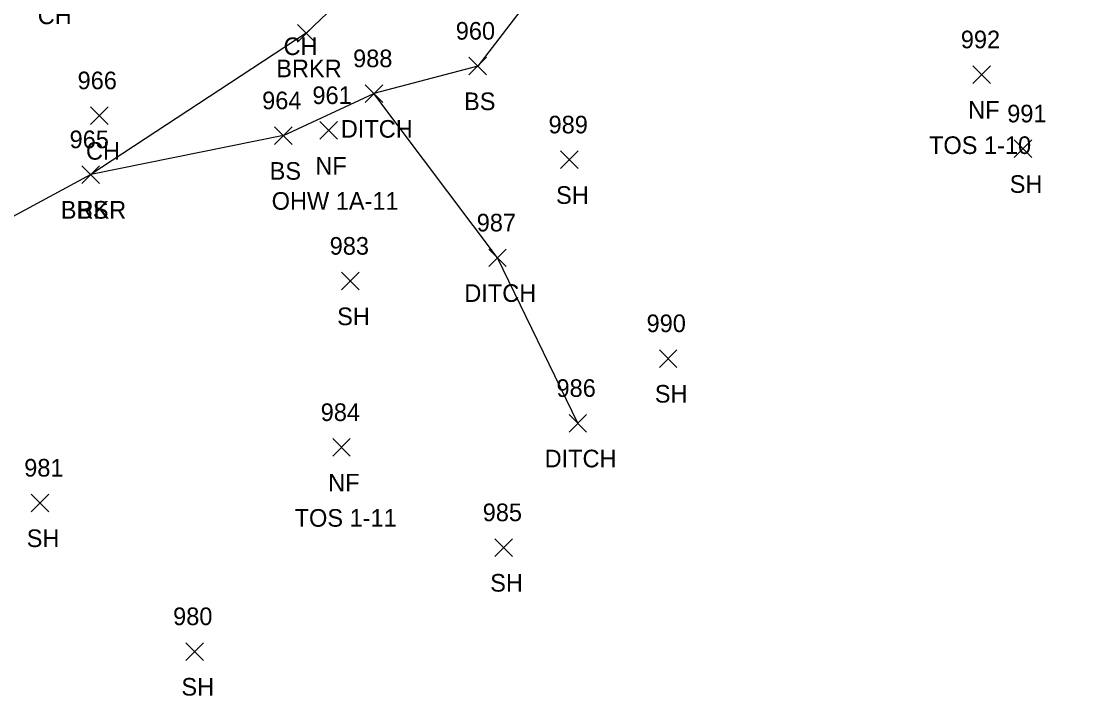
# Model space of a CAD drawing. Extents: x 1528286 to 1556263, y 492387 to 508952.
# Drawn here: x 1528421 to 1528541.2, y 492460.9 to 492537.5 of the extents above; entities that cross this region are included whole.
import ezdxf

# ---------------------------------------------------------------- set-up
doc = ezdxf.new("R2010")
doc.units = 0
for name, color, linetype in [('D_A', 7, 'Continuous'), ('D_I', 7, 'Continuous'), ('D_TIC', 7, 'Continuous'), ('DD', 7, 'Continuous'), ('L_A', 7, 'Continuous'), ('L_C', 7, 'Continuous'), ('L_I', 7, 'Continuous'), ('L_TIC', 7, 'Continuous'), ('LAWE', 7, 'Continuous'), ('LELB', 7, 'Continuous')]:
    doc.layers.add(name, color=color, linetype=linetype)

msp = doc.modelspace()

# ---------------------------------------------------------------- linework, layer by layer
at = {"layer": 'D_TIC'}
for points in [[(1528460.08, 492528.26), (1528462.08, 492530.26)], [(1528462.08, 492528.26), (1528460.08, 492530.26)], [(1528460.08, 492528.26), (1528462.08, 492530.26)], [(1528462.08, 492528.26), (1528460.08, 492530.26)], [(1528474.11, 492509.62), (1528476.11, 492511.62)], [(1528476.11, 492509.62), (1528474.11, 492511.62)], [(1528474.11, 492509.62), (1528476.11, 492511.62)], [(1528476.11, 492509.62), (1528474.11, 492511.62)], [(1528483.23, 492490.84), (1528485.23, 492492.84)], [(1528485.23, 492490.84), (1528483.23, 492492.84)], [(1528483.23, 492490.84), (1528485.23, 492492.84)], [(1528485.23, 492490.84), (1528483.23, 492492.84)]]:
    msp.add_lwpolyline(points, dxfattribs=at)
at = {"layer": 'DD'}
msp.add_lwpolyline([(1528484.23, 492491.84), (1528475.11, 492510.62), (1528461.08, 492529.26)], dxfattribs=at)
msp.add_lwpolyline([(1528484.23, 492491.84), (1528475.11, 492510.62), (1528461.08, 492529.26)], dxfattribs=at)
at = {"layer": 'L_TIC'}
for points in [[(1528452.39, 492535.12), (1528454.39, 492537.12)], [(1528454.39, 492535.12), (1528452.39, 492537.12)], [(1528452.39, 492535.12), (1528454.39, 492537.12)], [(1528454.39, 492535.12), (1528452.39, 492537.12)], [(1528471.87, 492531.39), (1528473.87, 492533.39)], [(1528473.87, 492531.39), (1528471.87, 492533.39)], [(1528471.87, 492531.39), (1528473.87, 492533.39)], [(1528473.87, 492531.39), (1528471.87, 492533.39)], [(1528529.09, 492530.41), (1528531.09, 492532.41)], [(1528531.09, 492530.41), (1528529.09, 492532.41)], [(1528529.09, 492530.41), (1528531.09, 492532.41)], [(1528531.09, 492530.41), (1528529.09, 492532.41)], [(1528428.88, 492525.76), (1528430.88, 492527.76)], [(1528430.88, 492525.76), (1528428.88, 492527.76)], [(1528428.88, 492525.76), (1528430.88, 492527.76)], [(1528430.88, 492525.76), (1528428.88, 492527.76)], [(1528454.94, 492524.08), (1528456.94, 492526.08)], [(1528456.94, 492524.08), (1528454.94, 492526.08)], [(1528454.94, 492524.08), (1528456.94, 492526.08)], [(1528456.94, 492524.08), (1528454.94, 492526.08)], [(1528449.79, 492523.49), (1528451.79, 492525.49)], [(1528451.79, 492523.49), (1528449.79, 492525.49)], [(1528449.79, 492523.49), (1528451.79, 492525.49)], [(1528451.79, 492523.49), (1528449.79, 492525.49)], [(1528533.79, 492522), (1528535.79, 492524)], [(1528535.79, 492522), (1528533.79, 492524)], [(1528533.79, 492522), (1528535.79, 492524)], [(1528535.79, 492522), (1528533.79, 492524)], [(1528482.28, 492520.75), (1528484.28, 492522.75)], [(1528484.28, 492520.75), (1528482.28, 492522.75)], [(1528482.28, 492520.75), (1528484.28, 492522.75)], [(1528484.28, 492520.75), (1528482.28, 492522.75)], [(1528427.92, 492519.07), (1528429.92, 492521.07)], [(1528429.92, 492519.07), (1528427.92, 492521.07)], [(1528427.92, 492519.07), (1528429.92, 492521.07)], [(1528429.92, 492519.07), (1528427.92, 492521.07)], [(1528427.92, 492519.07), (1528429.92, 492521.07)], [(1528429.92, 492519.07), (1528427.92, 492521.07)], [(1528427.92, 492519.07), (1528429.92, 492521.07)], [(1528429.92, 492519.07), (1528427.92, 492521.07)], [(1528457.41, 492506.98), (1528459.41, 492508.98)], [(1528459.41, 492506.98), (1528457.41, 492508.98)], [(1528457.41, 492506.98), (1528459.41, 492508.98)], [(1528459.41, 492506.98), (1528457.41, 492508.98)], [(1528493.49, 492498.19), (1528495.49, 492500.19)], [(1528495.49, 492498.19), (1528493.49, 492500.19)], [(1528493.49, 492498.19), (1528495.49, 492500.19)], [(1528495.49, 492498.19), (1528493.49, 492500.19)], [(1528456.39, 492488.1), (1528458.39, 492490.1)], [(1528458.39, 492488.1), (1528456.39, 492490.1)], [(1528456.39, 492488.1), (1528458.39, 492490.1)], [(1528458.39, 492488.1), (1528456.39, 492490.1)], [(1528422.15, 492481.79), (1528424.15, 492483.79)], [(1528424.15, 492481.79), (1528422.15, 492483.79)], [(1528422.15, 492481.79), (1528424.15, 492483.79)], [(1528424.15, 492481.79), (1528422.15, 492483.79)], [(1528474.8, 492476.73), (1528476.8, 492478.73)], [(1528476.8, 492476.73), (1528474.8, 492478.73)], [(1528474.8, 492476.73), (1528476.8, 492478.73)], [(1528476.8, 492476.73), (1528474.8, 492478.73)], [(1528439.72, 492464.93), (1528441.72, 492466.93)], [(1528441.72, 492464.93), (1528439.72, 492466.93)], [(1528439.72, 492464.93), (1528441.72, 492466.93)], [(1528441.72, 492464.93), (1528439.72, 492466.93)]]:
    msp.add_lwpolyline(points, dxfattribs=at)
at = {"layer": 'LAWE'}
msp.add_lwpolyline([(1528645.44, 492730.64), (1528651.62, 492718.64), (1528645.74, 492704.77), (1528631.81, 492684.8), (1528615.48, 492671.09), (1528597.13, 492648.32), (1528570.32, 492633.93), (1528549.93, 492614.14), (1528527.11, 492580.82), (1528486.91, 492550.69), (1528466.24, 492548.44), (1528453.39, 492536.12), (1528428.92, 492520.07), (1528405.49, 492507.44), (1528391.91, 492487.09), (1528384.54, 492464.65)], dxfattribs=at)
msp.add_lwpolyline([(1528645.44, 492730.64), (1528651.62, 492718.64), (1528645.74, 492704.77), (1528631.81, 492684.8), (1528615.48, 492671.09), (1528597.13, 492648.32), (1528570.32, 492633.93), (1528549.93, 492614.14), (1528527.11, 492580.82), (1528486.91, 492550.69), (1528466.24, 492548.44), (1528453.39, 492536.12), (1528428.92, 492520.07), (1528405.49, 492507.44), (1528391.91, 492487.09), (1528384.54, 492464.65)], dxfattribs=at)
at = {"layer": 'LELB'}
for points in [[(1528653.27, 492717.81), (1528645.74, 492704.77), (1528631.81, 492684.8), (1528615.48, 492671.09), (1528597.13, 492648.32), (1528570.32, 492633.93), (1528549.93, 492614.14), (1528527.11, 492580.82), (1528486.91, 492550.69), (1528472.87, 492532.39)], [(1528653.27, 492717.81), (1528645.74, 492704.77), (1528631.81, 492684.8), (1528615.48, 492671.09), (1528597.13, 492648.32), (1528570.32, 492633.93), (1528549.93, 492614.14), (1528527.11, 492580.82), (1528486.91, 492550.69), (1528472.87, 492532.39)], [(1528472.87, 492532.39), (1528461.08, 492529.26)], [(1528472.87, 492532.39), (1528461.08, 492529.26)], [(1528450.79, 492524.49), (1528461.08, 492529.26)], [(1528450.79, 492524.49), (1528461.08, 492529.26)], [(1528450.79, 492524.49), (1528428.92, 492520.07), (1528405.49, 492507.44), (1528391.91, 492487.09), (1528384.54, 492464.65)], [(1528450.79, 492524.49), (1528428.92, 492520.07), (1528405.49, 492507.44), (1528391.91, 492487.09), (1528384.54, 492464.65)]]:
    msp.add_lwpolyline(points, dxfattribs=at)

# ---------------------------------------------------------------- texts
at = {"layer": 'D_A'}
for p in [(1528457.31, 492524.26), (1528457.31, 492524.26), (1528471.34, 492505.62), (1528471.34, 492505.62), (1528480.46, 492486.84), (1528480.46, 492486.84)]:
    msp.add_text('DITCH', height=2, dxfattribs=at).set_placement(p)
at = {"layer": 'D_I'}
for s, p in [('988', (1528458.71, 492532.26)), ('988', (1528458.71, 492532.26)), ('987', (1528472.75, 492513.62)), ('987', (1528472.75, 492513.62)), ('986', (1528481.81, 492494.84)), ('986', (1528481.81, 492494.84))]:
    msp.add_text(s, height=2, dxfattribs=at).set_placement(p)
at = {"layer": 'L_A'}
for s, p in [('CH', (1528422.89, 492537.15)), ('CH', (1528422.89, 492537.15)), ('CH', (1528450.81, 492533.64)), ('CH', (1528450.81, 492533.64)), ('BRKR', (1528449.98, 492531.12)), ('BRKR', (1528449.98, 492531.12)), ('BS', (1528471.31, 492527.39)), ('BS', (1528471.31, 492527.39)), ('NF', (1528528.57, 492526.41)), ('NF', (1528528.57, 492526.41)), ('CH', (1528428.37, 492521.76)), ('CH', (1528428.37, 492521.76)), ('NF', (1528454.42, 492520.08)), ('NF', (1528454.42, 492520.08)), ('BS', (1528449.23, 492519.49)), ('BS', (1528449.23, 492519.49)), ('SH', (1528533.28, 492518)), ('SH', (1528533.28, 492518)), ('SH', (1528481.76, 492516.75)), ('SH', (1528481.76, 492516.75)), ('BRKR', (1528425.51, 492515.07)), ('BRKR', (1528425.51, 492515.07)), ('BS', (1528427.36, 492515.07)), ('BS', (1528427.36, 492515.07)), ('SH', (1528456.9, 492502.98)), ('SH', (1528456.9, 492502.98)), ('SH', (1528492.98, 492494.19)), ('SH', (1528492.98, 492494.19)), ('NF', (1528455.87, 492484.1)), ('NF', (1528455.87, 492484.1)), ('SH', (1528421.64, 492477.79)), ('SH', (1528421.64, 492477.79)), ('SH', (1528474.28, 492472.73)), ('SH', (1528474.28, 492472.73)), ('SH', (1528439.21, 492460.93)), ('SH', (1528439.21, 492460.93))]:
    msp.add_text(s, height=2, dxfattribs=at).set_placement(p)
at = {"layer": 'L_C'}
for s, p in [('TOS 1-10', (1528524.12, 492522.41)), ('TOS 1-10', (1528524.12, 492522.41)), ('OHW 1A-11', (1528449.46, 492516.08)), ('OHW 1A-11', (1528449.46, 492516.08)), ('TOS 1-11', (1528452.07, 492480.1)), ('TOS 1-11', (1528452.07, 492480.1))]:
    msp.add_text(s, height=2, dxfattribs=at).set_placement(p)
at = {"layer": 'L_I'}
for s, p in [('960', (1528470.37, 492535.39)), ('960', (1528470.37, 492535.39)), ('992', (1528527.73, 492534.41)), ('992', (1528527.73, 492534.41)), ('966', (1528427.42, 492529.76)), ('966', (1528427.42, 492529.76)), ('964', (1528448.38, 492527.49)), ('964', (1528448.38, 492527.49)), ('961', (1528454.09, 492528.08)), ('961', (1528454.09, 492528.08)), ('991', (1528533, 492526)), ('991', (1528533, 492526)), ('989', (1528480.91, 492524.75)), ('989', (1528480.91, 492524.75)), ('965', (1528426.51, 492523.07)), ('965', (1528426.51, 492523.07)), ('965', (1528426.51, 492523.07)), ('965', (1528426.51, 492523.07)), ('983', (1528456.05, 492510.98)), ('983', (1528456.05, 492510.98)), ('990', (1528492.04, 492502.19)), ('990', (1528492.04, 492502.19)), ('984', (1528455.03, 492492.1)), ('984', (1528455.03, 492492.1)), ('981', (1528421.36, 492485.79)), ('981', (1528421.36, 492485.79)), ('985', (1528473.43, 492480.73)), ('985', (1528473.43, 492480.73)), ('980', (1528438.27, 492468.93)), ('980', (1528438.27, 492468.93))]:
    msp.add_text(s, height=2, dxfattribs=at).set_placement(p)

doc.saveas('drawing.dxf')
